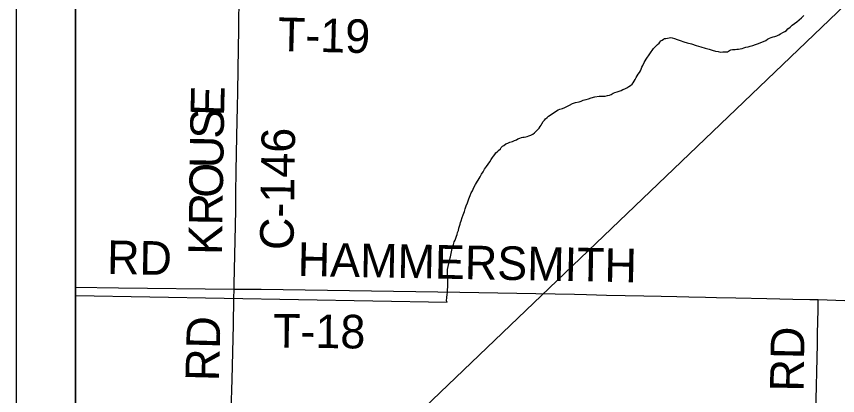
# Model space of a CAD drawing. Extents: x 0 to 34, y 0 to 22.
# Drawn here: x 23.417 to 24.806, y 15.253 to 15.894 of the extents above; entities that cross this region are included whole.
import ezdxf

# ---------------------------------------------------------------- set-up
doc = ezdxf.new("R2010")
doc.units = 0
for name, color, linetype in [('GM_X_County_Road', 7, 'Continuous'), ('GM_X_County_Road_Text', 7, 'Continuous'), ('GM_X_Minor_River', 7, 'Continuous'), ('GM_X_Township_Road', 7, 'Continuous'), ('GM_X_Township_Road_Text', 7, 'Continuous'), ('SH_Data', 7, 'Continuous')]:
    doc.layers.add(name, color=color, linetype=linetype)

msp = doc.modelspace()

# ---------------------------------------------------------------- linework, layer by layer
at = {"layer": 'GM_X_County_Road'}
for points in [[(23.7852, 15.4328), (23.7853, 15.4414), (23.7873, 15.5396), (23.7877, 15.5675), (23.788, 15.5949), (23.7886, 15.6322), (23.7895, 15.6918), (23.7907, 15.7415), (23.7913, 15.7657), (23.7918, 15.8055), (23.7928, 15.8726), (23.7937, 15.9329), (23.7937, 15.9351)], [(23.5167, 15.436), (23.5893, 15.4351), (23.7852, 15.4328)]]:
    msp.add_lwpolyline(points, dxfattribs=at)
at = {"layer": 'GM_X_Minor_River'}
for p, q in [((23.5167, 14.667), (25.1242, 16.2064)), ((23.5167, 15.4219), (24.1458, 15.4108))]:
    msp.add_line(p, q, dxfattribs=at)
for points in [[(24.7196, 15.8704), (24.7223, 15.873), (24.7262, 15.8759), (24.7297, 15.8792), (24.7333, 15.8821), (24.7375, 15.885), (24.7411, 15.8883), (24.745, 15.892), (24.7489, 15.8957)], [(24.3526, 15.7441), (24.3576, 15.7466), (24.363, 15.7483), (24.3687, 15.7496), (24.3726, 15.751), (24.3757, 15.7525), (24.378, 15.7531), (24.3807, 15.7538), (24.3845, 15.7548), (24.3891, 15.7562), (24.3953, 15.7583), (24.4026, 15.7592), (24.4083, 15.759), (24.4129, 15.7592), (24.4171, 15.7602), (24.4205, 15.7612), (24.4232, 15.7623), (24.4267, 15.7641), (24.4294, 15.7655), (24.4333, 15.7665), (24.4367, 15.7675), (24.4398, 15.769), (24.4429, 15.7704), (24.446, 15.7718), (24.4495, 15.7736), (24.453, 15.7758), (24.4561, 15.7772), (24.4588, 15.7798), (24.4604, 15.782), (24.462, 15.7846), (24.464, 15.7876), (24.4657, 15.7909), (24.4673, 15.7935), (24.4689, 15.7962), (24.4709, 15.7995), (24.4725, 15.8021), (24.4737, 15.8051), (24.4753, 15.8081), (24.4766, 15.8111), (24.479, 15.816), (24.4823, 15.8216), (24.495, 15.8398), (24.4986, 15.8439), (24.5013, 15.8464), (24.5041, 15.849), (24.5053, 15.8509), (24.5072, 15.8527), (24.5092, 15.8542), (24.5115, 15.8556), (24.5135, 15.8567), (24.5158, 15.857), (24.5184, 15.8573), (24.5211, 15.858), (24.5234, 15.8583), (24.5261, 15.8582), (24.5302, 15.8569), (24.5351, 15.8552), (24.54, 15.8532), (24.546, 15.8514), (24.5517, 15.8497), (24.5589, 15.8476), (24.5668, 15.845), (24.5747, 15.8429), (24.5823, 15.8403), (24.5891, 15.8386), (24.5943, 15.8369), (24.5996, 15.8356), (24.6042, 15.8347), (24.6083, 15.8338), (24.6121, 15.834), (24.6171, 15.8342), (24.6198, 15.8345), (24.6217, 15.8352), (24.6236, 15.8363), (24.6256, 15.8374), (24.6283, 15.8381), (24.6309, 15.8383), (24.6332, 15.8383), (24.6359, 15.8386), (24.6386, 15.8389), (24.6412, 15.8391), (24.6447, 15.8398), (24.6474, 15.8408), (24.6509, 15.8419), (24.6547, 15.8429), (24.6585, 15.8439), (24.6628, 15.8449), (24.6674, 15.8466), (24.6724, 15.8484), (24.6847, 15.8537), (24.6875, 15.8559), (24.6913, 15.8573), (24.694, 15.8587), (24.6971, 15.8597), (24.7002, 15.8604), (24.7033, 15.8614), (24.7068, 15.8628), (24.7099, 15.8646), (24.7134, 15.8668), (24.7168, 15.8686), (24.7196, 15.8704)], [(24.1458, 15.4108), (24.1447, 15.4128), (24.1453, 15.4188), (24.1454, 15.4234), (24.1459, 15.4272), (24.146, 15.4299), (24.1461, 15.4325), (24.1466, 15.4355), (24.1467, 15.439), (24.1468, 15.4431), (24.1466, 15.4477), (24.1464, 15.4542), (24.1462, 15.4599), (24.1464, 15.466), (24.1473, 15.4713), (24.1483, 15.4762), (24.1496, 15.4819), (24.1513, 15.4875), (24.1522, 15.4928), (24.1535, 15.4985), (24.1549, 15.5038), (24.1561, 15.5083), (24.1574, 15.5128), (24.1591, 15.5158), (24.1603, 15.5192), (24.1615, 15.5222), (24.1624, 15.5252), (24.1633, 15.5286), (24.1645, 15.532), (24.1654, 15.5357), (24.1667, 15.5395), (24.1675, 15.5429), (24.1684, 15.5452), (24.1692, 15.5482), (24.1709, 15.5538), (24.1726, 15.5587), (24.1747, 15.564), (24.1763, 15.5685), (24.178, 15.5734), (24.1801, 15.579), (24.1822, 15.5854), (24.1847, 15.5914), (24.1864, 15.5955), (24.1884, 15.5993), (24.1896, 15.6019), (24.1912, 15.6056), (24.1933, 15.6098), (24.2013, 15.6228), (24.2037, 15.6273), (24.2065, 15.6314), (24.209, 15.6359), (24.2122, 15.6403), (24.215, 15.6444), (24.2177, 15.6481), (24.2198, 15.6519), (24.2225, 15.6556), (24.2241, 15.6578), (24.2261, 15.6608), (24.2281, 15.6634), (24.2305, 15.6656), (24.2324, 15.6674), (24.2356, 15.6704), (24.2372, 15.6722), (24.2391, 15.6744), (24.2415, 15.6755), (24.245, 15.6784), (24.2481, 15.6798), (24.2519, 15.6812), (24.2562, 15.6826), (24.2596, 15.684), (24.2627, 15.6854), (24.2654, 15.6869), (24.2685, 15.6883), (24.2712, 15.6893), (24.2739, 15.6896), (24.2758, 15.69), (24.2789, 15.6902), (24.2812, 15.6909), (24.2839, 15.692), (24.287, 15.6934), (24.2904, 15.6948), (24.2936, 15.697), (24.2959, 15.6992), (24.2983, 15.7021), (24.3011, 15.7051), (24.303, 15.7077), (24.3047, 15.7103), (24.3059, 15.7125), (24.3083, 15.7166), (24.3103, 15.7189), (24.3122, 15.7211), (24.3146, 15.7229), (24.3173, 15.7255), (24.3216, 15.7284), (24.3309, 15.7342), (24.3337, 15.736), (24.3364, 15.737), (24.341, 15.7384), (24.3448, 15.7402), (24.3483, 15.7416), (24.3526, 15.7441)]]:
    msp.add_lwpolyline(points, dxfattribs=at)
at = {"layer": 'GM_X_Township_Road'}
for points in [[(23.5167, 18.4074), (23.5167, 14.1), (28.7673, 14.1), (28.7709, 14.3107), (28.7934, 15.3155), (28.8021, 16.3696)], [(23.7786, 15.1634), (23.7787, 15.1734), (23.7802, 15.2268), (23.7815, 15.2797), (23.7838, 15.3723), (23.7848, 15.4171), (23.7852, 15.4328)], [(23.7852, 15.4328), (23.8306, 15.4326), (24.1669, 15.4278), (24.2958, 15.4253)], [(24.2958, 15.4253), (24.3608, 15.424), (24.3813, 15.4236), (24.4155, 15.4227), (24.4783, 15.4215), (24.5075, 15.4209), (24.5342, 15.4204), (24.5547, 15.4198), (24.5827, 15.4191), (24.6014, 15.4187), (24.6343, 15.4179), (24.6865, 15.4168), (24.7306, 15.416), (24.7592, 15.4153), (24.7736, 15.4149)], [(24.7686, 14.9148), (24.7669, 14.922), (24.7657, 14.9294), (24.7652, 14.9359), (24.7649, 14.9429), (24.765, 14.9534), (24.7662, 14.9994), (24.7664, 15.0243), (24.7675, 15.1052), (24.7684, 15.1412), (24.7696, 15.2221), (24.7721, 15.3396), (24.7725, 15.3577), (24.7733, 15.3975), (24.7735, 15.408), (24.7736, 15.4149)], [(24.7736, 15.4149), (24.8183, 15.4137)]]:
    msp.add_lwpolyline(points, dxfattribs=at)
at = {"layer": 'SH_Data'}
for points in [[(23.4167, 21), (30.4167, 21), (30.4167, 14), (23.4167, 14)], [(23.5167, 20.9), (30.3167, 20.9), (30.3167, 14.1), (23.5167, 14.1)]]:
    msp.add_lwpolyline(points, close=True, dxfattribs=at)

# ---------------------------------------------------------------- texts
at = {"layer": 'GM_X_County_Road_Text'}
for s, height, rotation, p in [('E', 0.0568, 88.622, (23.768, 15.7252)), ('S', 0.0568, 89.1233, (23.7674, 15.687)), ('C-146', 0.05682, 89.1818, (23.8855, 15.4985)), ('U', 0.0568, 89.1312, (23.7667, 15.637)), ('O', 0.0568, 89.1329, (23.7659, 15.587)), ('R', 0.0568, 89.1315, (23.7652, 15.5403)), ('K', 0.0568, 89.133, (23.7644, 15.4903)), ('RD', 0.05682, 359.0188, (23.5697, 15.4584))]:
    msp.add_text(s, height=height, rotation=rotation, dxfattribs=at).set_placement(p)
at = {"layer": 'GM_X_Township_Road_Text'}
for s, height, rotation, p in [('T-19', 0.05682, 358.585, (23.8585, 15.8358)), ('HAMMERSMITH', 0.056818, 358.9155, (23.8923, 15.4551)), ('RD', 0.05682, 88.5383, (23.7594, 15.2765)), ('T-18', 0.05682, 359.2931, (23.8506, 15.3341)), ('RD', 0.05682, 89.0127, (24.7486, 15.259))]:
    msp.add_text(s, height=height, rotation=rotation, dxfattribs=at).set_placement(p)

doc.saveas('drawing.dxf')
